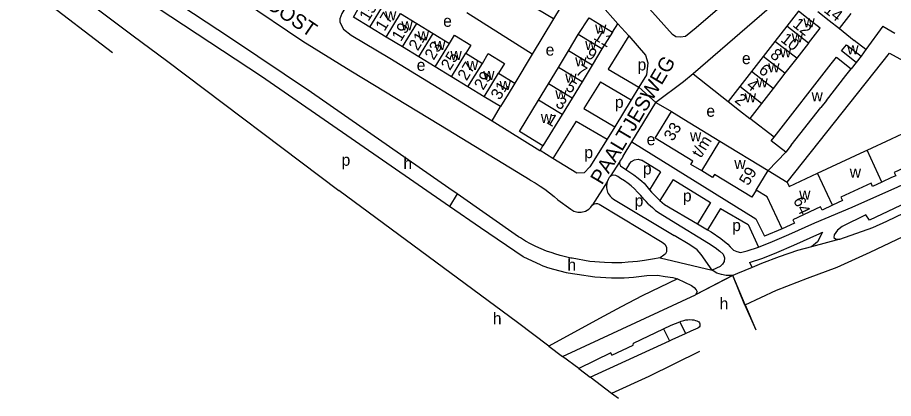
# Model space of a CAD drawing. Extents: x 158356 to 159894, y 383831 to 385260.
# Drawn here: x 158701.2 to 159000.7, y 383830.9 to 383961.2 of the extents above; entities that cross this region are included whole.
import ezdxf

# ---------------------------------------------------------------- set-up
doc = ezdxf.new("R2010")
doc.units = 0
for name, color, linetype in [('BLT_Basislijn', 7, 'Continuous'), ('BLT_Bebouwing', 7, 'Continuous'), ('BLT_Centroide', 7, 'Continuous'), ('BLT_Huisnummer', 7, 'Continuous'), ('BLT_Huisnummer_ tussenligend', 7, 'Continuous'), ('BLT_Huisnummer_reeks', 7, 'Continuous'), ('BLT_Onderverdeling_panden', 7, 'Continuous'), ('BLT_Straatnaam', 7, 'Continuous'), ('BLT_Vlakafsluiter', 7, 'Continuous')]:
    doc.layers.add(name, color=color, linetype=linetype)

msp = doc.modelspace()

# ---------------------------------------------------------------- linework, layer by layer
at = {"layer": 'BLT_Basislijn'}
for p, q in [((158733.69, 383949.17), (158656.47, 384008.34)), ((158964.85, 383970.22), (158932.17, 383941.98)), ((158900.43, 383965.89), (158906.43, 383959.08)), ((158877.21, 383948.71), (158854.87, 383962.79)), ((158884.43, 383960.73), (158877.21, 383948.71)), ((158904.67, 383956.2), (158906.43, 383959.08)), ((158982.23, 383957.43), (158987.21, 383953.4)), ((158997.04, 383958.25), (159001.16, 383955.84)), ((158910.26, 383954.96), (158903.18, 383943.54)), ((158991.28, 383950.26), (158987.21, 383953.4)), ((158877.21, 383948.71), (158871.25, 383938.8)), ((158964.3, 383904.94), (158999.29, 383949)), ((158991.28, 383950.26), (158989.64, 383947.99)), ((158999.29, 383949), (159026.07, 383934.41)), ((158987.98, 383945.88), (158986.26, 383943.69)), ((158903.18, 383943.54), (158913.66, 383937.37)), ((158900.54, 383939.29), (158894.84, 383930.09)), ((158900.54, 383939.29), (158911.04, 383933.11)), ((158932.17, 383941.98), (158944.12, 383932.51)), ((158913.66, 383937.37), (158911.04, 383933.11)), ((158863.52, 383925.87), (158866.36, 383930.76)), ((158911.04, 383933.11), (158905.38, 383923.88)), ((158911.26, 383918.68), (158919.49, 383932.21)), ((158919.49, 383932.21), (158924.77, 383929.08)), ((158894.84, 383930.09), (158905.38, 383923.88)), ((158892.2, 383925.84), (158884.28, 383913.06)), ((158892.2, 383925.84), (158902.76, 383919.62)), ((158959.92, 383920.35), (158951.54, 383926.73)), ((158876.46, 383905.62), (158845.77, 383924.27)), ((158905.38, 383923.88), (158902.76, 383919.62)), ((158908.28, 383913.84), (158911.26, 383918.68)), ((158879.88, 383915.72), (158880.83, 383917.4)), ((158884.28, 383913.06), (158879.88, 383915.72)), ((158921.07, 383908.42), (158914.49, 383912.44)), ((158910.33, 383911.08), (158909.21, 383909.23)), ((158921.07, 383908.42), (158917.27, 383902.35)), ((158925.34, 383905.81), (158920.82, 383898.6)), ((158925.34, 383905.81), (158938.13, 383897.97)), ((158872.16, 383856.91), (158811.09, 383902.1)), ((158851.48, 383900.89), (158848.65, 383902.86)), ((158872.54, 383886.2), (158851.48, 383900.89)), ((158885.96, 383898.88), (158890.33, 383895.73)), ((158905.02, 383899.09), (158925.71, 383886.66)), ((158938.13, 383897.97), (158933.64, 383890.68)), ((158941.59, 383895.96), (158937.09, 383888.66)), ((158941.59, 383895.96), (158951.06, 383890.42)), ((158951.06, 383890.42), (158954.57, 383882.71)), ((158962.68, 383888.99), (158956.54, 383886.44)), ((158951.51, 383877.47), (158952.37, 383875.72)), ((158887.51, 383845.34), (158932.98, 383866.36)), ((158882.83, 383848.86), (158872.16, 383856.91)), ((158927.61, 383857.11), (158929.6, 383853.17)), ((158922.02, 383854.74), (158924.07, 383850.6)), ((158882.83, 383848.86), (158887.51, 383845.34)), ((158893.06, 383841.15), (158887.51, 383845.34)), ((158893.06, 383841.15), (158897.01, 383838.18)), ((158904.33, 383832.66), (158897.01, 383838.18)), ((158906.63, 383830.93), (158904.33, 383832.66))]:
    msp.add_line(p, q, dxfattribs=at)
for points in [[(158658.2, 384017.9), (158708.3, 383979.52), (158740.71, 383955.02), (158752.16, 383946.49), (158811.09, 383902.1)], [(158845.77, 383924.27), (158815.12, 383942.93), (158798.74, 383953.03), (158757.49, 383980.97), (158706.27, 384015.3)], [(158957.8, 384013.41), (158976.75, 384003.11), (158977.59, 384001.79), (158978.2, 383998.68), (158977.76, 383997.43), (158976.65, 383995.8), (158964.84, 383984.91), (158933.18, 383957.74), (158929.53, 383954.78), (158927.87, 383954.47), (158926.29, 383954.61), (158925.11, 383955.45), (158909.46, 383973.08)], [(158848.65, 383902.86), (158801.74, 383935.63), (158773.98, 383954.21), (158744.72, 383973.5), (158719.42, 383989.69)], [(158848.91, 383896.59), (158784.62, 383941.05), (158735.9, 383973.27)], [(158814.16, 383966.01), (158812.13, 383962.64), (158811.34, 383960.74), (158811.34, 383959.69), (158812.63, 383957.28), (158815.24, 383955.2), (158828.49, 383947.37), (158863.52, 383925.87)], [(158906.43, 383959.08), (158910.26, 383954.96)], [(158997.04, 383958.25), (158991.28, 383950.26)], [(158910.26, 383954.96), (158915.92, 383948.41), (158916.7, 383945.79), (158916.27, 383941.62), (158913.66, 383937.37)], [(158932.17, 383941.98), (158928.94, 383939.19), (158919.49, 383932.21)], [(158863.52, 383925.87), (158879.74, 383915.8), (158879.88, 383915.72)], [(158949.95, 383862.91), (158960.72, 383867.95), (158971.31, 383872.04), (158981.41, 383875.89), (158992.71, 383880.94), (159088.93, 383926.66)], [(158973.85, 383891.02), (158986.52, 383896.41), (159002.13, 383903.34), (159020.44, 383911.89), (159042.83, 383922.34), (159045.95, 383923.82)], [(158902.76, 383919.62), (158896.92, 383910.11), (158894.94, 383908.15), (158892.48, 383908.05), (158884.28, 383913.06)], [(158911.26, 383918.68), (158953.65, 383892.43), (158956.54, 383886.44)], [(159053.28, 383920.71), (158992.49, 383891.93), (158991.27, 383893.7), (158983.13, 383889.76), (158981.5, 383888.54), (158980.42, 383886.91), (158980.28, 383885.96), (158980.96, 383885.42), (158982.35, 383885.39)], [(158982.35, 383885.39), (158993.58, 383889.36), (158998.46, 383891.53), (159004.3, 383894.38), (159021.53, 383902.66), (159051.79, 383917.05)], [(158908.28, 383913.84), (158907.77, 383913.05), (158907.29, 383912.31), (158907.1, 383911.94)], [(158910.33, 383911.08), (158911.07, 383911.99), (158912.15, 383912.6), (158913.38, 383912.74), (158914.49, 383912.44)], [(158957.8, 383908.91), (158963.84, 383915.17)], [(158907.1, 383911.94), (158907.02, 383911.45), (158907.1, 383910.97), (158907.4, 383910.45), (158909.21, 383909.23)], [(158903.83, 383906.89), (158903.5, 383906.48), (158903.13, 383905.85), (158902.83, 383905.07)], [(158916.99, 383897.41), (158916.12, 383898.28), (158915.34, 383899.09), (158914.3, 383900.32), (158913.22, 383901.54), (158912.18, 383902.66), (158911.03, 383903.66), (158909.96, 383904.51), (158908.73, 383905.36), (158907.36, 383906.18), (158906.43, 383906.85), (158905.73, 383907.22), (158905.06, 383907.33), (158904.35, 383907.18), (158903.83, 383906.89)], [(158909.21, 383909.23), (158911.92, 383907.48), (158913.41, 383906.33), (158914.6, 383905.29), (158915.41, 383904.55), (158917.27, 383902.35)], [(158876.46, 383905.62), (158878.18, 383904.64), (158879.87, 383903.59), (158881.51, 383902.47), (158883.1, 383901.28), (158884.64, 383900.03), (158885.96, 383898.88)], [(158902.83, 383905.07), (158902.68, 383904.48), (158902.57, 383903.7), (158902.57, 383903.06), (158902.72, 383902.4), (158902.94, 383901.54), (158903.2, 383900.99), (158903.8, 383900.09), (158904.39, 383899.58), (158905.02, 383899.09)], [(158917.27, 383902.35), (158917.94, 383901.54)], [(158917.94, 383901.54), (158920.82, 383898.6)], [(158897.82, 383897.14), (158898.33, 383897.49), (158898.93, 383897.64), (158899.54, 383897.64), (158900.04, 383897.39), (158921.63, 383884.44), (158922.48, 383883.69), (158923.04, 383882.74), (158923.14, 383881.88), (158923.09, 383881.08), (158922.79, 383880.37), (158922.22, 383879.93), (158920.92, 383879.06)], [(158916.99, 383897.41), (158918.29, 383896.2), (158919.37, 383895.27), (158920.89, 383894.23), (158924.82, 383891.85)], [(158920.82, 383898.6), (158922.44, 383897.33), (158933.64, 383890.68)], [(158880.24, 383876.48), (158874.09, 383879.35), (158859.5, 383889.27), (158848.91, 383896.59)], [(158890.33, 383895.73), (158891.43, 383895.02), (158892.74, 383894.62), (158893.95, 383894.62), (158895.41, 383894.97), (158896.52, 383895.63), (158897.22, 383896.33), (158897.82, 383897.14)], [(158924.82, 383891.85), (158937.43, 383884.08), (158939.77, 383882.63), (158941.33, 383881.29), (158942.44, 383880.29), (158942.89, 383879.06), (158942.78, 383877.73), (158942.22, 383876.84), (158941.44, 383876.06), (158938.68, 383874.81)], [(158933.64, 383890.68), (158937.09, 383888.66)], [(158937.09, 383888.66), (158938.34, 383887.93), (158941.68, 383885.7), (158944.02, 383883.7), (158944.91, 383882.8), (158946.02, 383881.69), (158947.14, 383881.25), (158948.36, 383880.91), (158950.62, 383881.4)], [(158954.57, 383882.71), (158959.32, 383884.59), (158964.95, 383887.02), (158973.85, 383891.02)], [(158883.96, 383880.7), (158882.08, 383881.37), (158880.22, 383882.11), (158878.39, 383882.94), (158876.6, 383883.83), (158874.84, 383884.79), (158873.13, 383885.83), (158872.54, 383886.2)], [(158938.68, 383874.81), (158934.94, 383880.2), (158933.6, 383881.76), (158931.04, 383883.43), (158925.71, 383886.66)], [(158951.51, 383877.47), (158955.98, 383878.97), (158960.85, 383880.89), (158966.57, 383883.36), (158975.49, 383887.37)], [(158975.49, 383887.37), (158976.48, 383887.86), (158974.72, 383884.47), (158972.64, 383882.77)], [(158950.62, 383881.4), (158954.57, 383882.71)], [(158972.64, 383882.77), (158967.89, 383881.54), (158961.65, 383879.42), (158955.53, 383877.08), (158952.37, 383875.72)], [(158890.81, 383878.9), (158890.4, 383878.97), (158888.53, 383879.36), (158886.69, 383879.84), (158884.86, 383880.39), (158883.96, 383880.7)], [(158880.24, 383876.48), (158882.35, 383875.76), (158884.48, 383875.12), (158886.64, 383874.55), (158888.81, 383874.07), (158891, 383873.66), (158892.57, 383873.43)], [(158920.92, 383879.06), (158918.26, 383878.56), (158915.54, 383878.11), (158913.17, 383877.75), (158910, 383877.5), (158907.79, 383877.35), (158904.37, 383877.3), (158901.85, 383877.4), (158896.82, 383877.75), (158890.81, 383878.9)], [(158892.57, 383873.43), (158898.58, 383872.58), (158904.27, 383872.23), (158908.64, 383872.18), (158911.76, 383872.38), (158914.58, 383872.73), (158916.39, 383873.03)], [(158945.63, 383872.96), (158943.51, 383872.96), (158941.84, 383873.29), (158940.28, 383873.74), (158938.68, 383874.81)], [(158952.37, 383875.72), (158947.36, 383873.65), (158945.78, 383872.98)], [(158926.81, 383871.89), (158914.79, 383866.01), (158907.55, 383862.24), (158900.15, 383858.31), (158882.83, 383848.86)], [(158916.39, 383873.03), (158920.04, 383873.11)], [(158920.04, 383873.11), (158922.64, 383872.66), (158925.21, 383872.36), (158926.81, 383871.89)], [(158926.81, 383871.89), (158929.26, 383870.73), (158931.6, 383869.62), (158932.6, 383868.84), (158933.27, 383868.06), (158933.6, 383867.39), (158933.03, 383866.44)], [(158945.74, 383872.96), (158945.63, 383872.96)], [(158945.78, 383872.98), (158945.74, 383872.96)], [(158933.03, 383866.44), (158932.98, 383866.36)], [(158949.9, 383862.89), (158949.95, 383862.91)], [(158922.02, 383854.74), (158924.65, 383855.96), (158927.61, 383857.11)], [(158927.61, 383857.11), (158928.16, 383857.32), (158929.06, 383857.65), (158929.68, 383857.79), (158930.35, 383857.88), (158931.01, 383857.92), (158931.81, 383857.88), (158932.38, 383857.79), (158932.97, 383857.66), (158933.49, 383857.51), (158933.92, 383857.31), (158934.18, 383857.17), (158934.41, 383856.85), (158934.52, 383856.42), (158934.54, 383855.93), (158934.44, 383855.63), (158934.29, 383855.36), (158933.96, 383855.14)], [(158911.68, 383849.18), (158911.77, 383849.85), (158922.02, 383854.74)], [(158924.07, 383850.6), (158925.06, 383851.06), (158929.6, 383853.17)], [(158929.6, 383853.17), (158931.55, 383854.08), (158933.96, 383855.14)], [(158897.01, 383838.18), (158924.07, 383850.6)], [(158904.45, 383845.74), (158904.07, 383846.53), (158893.06, 383841.15)], [(158934.4, 383846.95), (158917.1, 383838.48), (158904.33, 383832.66)], [(158904.45, 383845.74), (158911.68, 383849.18)]]:
    msp.add_lwpolyline(points, dxfattribs=at)
at = {"layer": 'BLT_Bebouwing'}
for p, q in [((158884.43, 383960.73), (158878.84, 383964.13)), ((158832.09, 383962.61), (158837.69, 383959.2)), ((158982.23, 383957.43), (158986.27, 383962.6)), ((158827.21, 383954.57), (158821.7, 383957.91)), ((158837.69, 383959.2), (158843.28, 383955.8)), ((158964.2, 383958.23), (158960.18, 383953.09)), ((158832.8, 383951.17), (158827.21, 383954.57)), ((158843.28, 383955.8), (158848.87, 383952.4)), ((158889.53, 383949.8), (158892.93, 383955.41)), ((158904.67, 383956.2), (158901.03, 383950.49)), ((158960.18, 383953.09), (158956.17, 383947.94)), ((158971.61, 383952.44), (158967.6, 383947.3)), ((158838.39, 383947.77), (158832.8, 383951.17)), ((158854.47, 383949), (158860.15, 383945.55)), ((158886.13, 383944.19), (158889.53, 383949.8)), ((158901.03, 383950.49), (158897.62, 383944.89)), ((158843.99, 383944.36), (158838.39, 383947.77)), ((158956.17, 383947.94), (158952.15, 383942.8)), ((158967.6, 383947.3), (158963.58, 383942.16)), ((158989.64, 383947.99), (158987.98, 383945.88)), ((158849.58, 383940.97), (158843.99, 383944.36)), ((158882.72, 383938.59), (158886.13, 383944.19)), ((158897.62, 383944.89), (158894.22, 383939.28)), ((158952.15, 383942.8), (158948.14, 383937.66)), ((158984.46, 383941.4), (158986.26, 383943.69)), ((158855.18, 383937.57), (158849.58, 383940.97)), ((158865.65, 383942.2), (158871.25, 383938.8)), ((158894.22, 383939.28), (158890.82, 383933.67)), ((158963.58, 383942.16), (158959.57, 383937.01)), ((158977.74, 383932.85), (158984.46, 383941.4)), ((158860.77, 383934.16), (158855.18, 383937.57)), ((158879.32, 383932.98), (158882.72, 383938.59)), ((158948.14, 383937.66), (158944.12, 383932.51)), ((158959.57, 383937.01), (158955.55, 383931.87)), ((158866.36, 383930.76), (158860.77, 383934.16)), ((158890.82, 383933.67), (158887.41, 383928.07)), ((158955.55, 383931.87), (158951.54, 383926.73)), ((158965.7, 383917.54), (158975.88, 383930.49)), ((158977.74, 383932.85), (158975.88, 383930.49)), ((158887.41, 383928.07), (158880.83, 383917.4)), ((158941.36, 383918.95), (158957.8, 383908.91)), ((158965.7, 383917.54), (158963.84, 383915.17)), ((158974.7, 383907.99), (158990.88, 383915.51)), ((158990.88, 383915.51), (158991.69, 383915.89)), ((158979.8, 383897), (158976.32, 383895.39))]:
    msp.add_line(p, q, dxfattribs=at)
for points in [[(158889.32, 383968.77), (158886.73, 383964.5), (158884.43, 383960.73)], [(158821.7, 383957.91), (158816.02, 383961.37), (158817.58, 383963.93)], [(158971.61, 383952.44), (158975.62, 383957.58), (158972.15, 383960.29), (158968.21, 383963.37), (158964.2, 383958.23)], [(158974.79, 383963.24), (158978.73, 383960.16), (158982.23, 383957.43)], [(158892.93, 383955.41), (158896.62, 383961.1), (158897.23, 383960.73), (158904.67, 383956.2)], [(158848.87, 383952.4), (158850.57, 383955.18), (158856.16, 383951.78), (158854.47, 383949)], [(158987.98, 383945.88), (158982.97, 383949.81), (158984.63, 383951.93), (158989.64, 383947.99)], [(158860.15, 383945.55), (158862.17, 383948.88), (158867.74, 383945.5), (158865.65, 383942.2)], [(158959.92, 383920.35), (158979.4, 383945.38), (158981.2, 383947.67), (158986.26, 383943.69)], [(158871.25, 383938.8), (158868.96, 383935.04), (158866.36, 383930.76)], [(158880.83, 383917.4), (158872.81, 383922.3), (158879.32, 383932.98)], [(158944.12, 383932.51), (158948.06, 383929.44), (158951.54, 383926.73)], [(158935.13, 383908.74), (158931.41, 383911.01), (158932.07, 383912.1), (158919.2, 383919.95), (158924.77, 383929.08)], [(158924.77, 383929.08), (158929.04, 383926.48), (158941.36, 383918.95)], [(158991.69, 383915.89), (159000, 383919.75), (159009.73, 383924.32)], [(158963.84, 383915.17), (158958.9, 383919.05), (158959.92, 383920.35)], [(159014.85, 383913.41), (159010.96, 383911.58), (159010.43, 383912.72), (159000.92, 383908.26), (159001.45, 383907.13), (159000, 383906.46), (158996.77, 383904.96)], [(158953.73, 383902.24), (158952.24, 383899.79), (158939.51, 383907.55), (158938.85, 383906.47), (158935.13, 383908.74)], [(158957.8, 383908.91), (158964.3, 383904.94)], [(158964.3, 383904.94), (158964.98, 383903.47), (158974.7, 383907.99)], [(158996.77, 383904.96), (158993.54, 383903.46), (158993.03, 383904.56), (158982.75, 383899.78), (158983.28, 383898.62), (158979.8, 383897)], [(158962.68, 383888.99), (158957.55, 383899.91), (158953.73, 383902.24)], [(158976.32, 383895.39), (158975.8, 383896.52), (158966.25, 383892.08), (158966.8, 383890.9), (158962.68, 383888.99)]]:
    msp.add_lwpolyline(points, dxfattribs=at)
at = {"layer": 'BLT_Onderverdeling_panden'}
for p, q in [((158821.7, 383957.91), (158826.59, 383965.95)), ((158827.21, 383954.57), (158832.09, 383962.61)), ((158832.8, 383951.17), (158837.69, 383959.2)), ((158971.61, 383952.44), (158964.2, 383958.23)), ((158838.39, 383947.77), (158843.28, 383955.8)), ((158901.03, 383950.49), (158892.93, 383955.41)), ((158843.99, 383944.36), (158848.87, 383952.4)), ((158967.6, 383947.3), (158960.18, 383953.09)), ((158849.58, 383940.97), (158854.47, 383949)), ((158897.62, 383944.89), (158889.53, 383949.8)), ((158855.18, 383937.57), (158860.15, 383945.55)), ((158963.58, 383942.16), (158956.17, 383947.94)), ((158894.22, 383939.28), (158886.13, 383944.19)), ((158959.57, 383937.01), (158952.15, 383942.8)), ((158860.77, 383934.16), (158865.65, 383942.2)), ((158890.82, 383933.67), (158882.72, 383938.59)), ((158955.55, 383931.87), (158948.14, 383937.66)), ((158887.41, 383928.07), (158879.32, 383932.98)), ((158935.13, 383908.74), (158941.36, 383918.95)), ((158996.77, 383904.96), (158991.69, 383915.89)), ((158953.73, 383902.24), (158957.8, 383908.91)), ((158979.8, 383897), (158974.7, 383907.99))]:
    msp.add_line(p, q, dxfattribs=at)
at = {"layer": 'BLT_Vlakafsluiter'}
for p, q in [((158913.66, 383937.37), (158919.49, 383932.21)), ((158907.1, 383911.94), (158903.83, 383906.89)), ((158902.83, 383905.07), (158897.82, 383897.14)), ((158851.48, 383900.89), (158848.91, 383896.59)), ((158982.35, 383885.39), (158972.64, 383882.77)), ((158920.92, 383879.06), (158938.68, 383874.81)), ((158945.74, 383872.96), (158932.98, 383866.36)), ((158945.63, 383872.96), (158933.03, 383866.44)), ((158949.9, 383862.89), (158945.74, 383872.96)), ((158949.95, 383862.91), (158945.78, 383872.98)), ((158949.9, 383862.89), (158953.58, 383854.42)), ((158949.95, 383862.91), (158953.63, 383854.44))]:
    msp.add_line(p, q, dxfattribs=at)

# ---------------------------------------------------------------- texts
at = {"layer": 'BLT_Centroide'}
for s, p in [('w', (158826.86, 383960.28)), ('e', (158846.73, 383958.06)), ('w', (158969.91, 383957.91)), ('w', (158832.45, 383956.88)), ('w', (158898.68, 383955.75)), ('w', (158838.03, 383953.48)), ('w', (158965.9, 383952.75)), ('w', (158843.64, 383950.09)), ('e', (158881.77, 383948.21)), ('w', (158895.27, 383950.16)), ('w', (158984.88, 383948.63)), ('w', (158849.23, 383946.69)), ('e', (158948.88, 383945.29)), ('w', (158961.88, 383947.62)), ('e', (158837.68, 383942.99)), ('w', (158854.83, 383943.28)), ('w', (158891.88, 383944.53)), ('p', (158913.2, 383943.15)), ('w', (158957.87, 383942.47)), ('w', (158860.42, 383939.88)), ('w', (158866.02, 383936.48)), ('w', (158888.48, 383938.94)), ('w', (158953.85, 383937.34)), ('w', (158885.07, 383933.31)), ('p', (158905.45, 383930.34)), ('w', (158949.84, 383932.19)), ('w', (158972.68, 383932.62)), ('e', (158936.72, 383927.29)), ('w', (158880.11, 383925.17)), ('w', (158931.11, 383918.91)), ('e', (158916.3, 383917.56)), ('p', (158895, 383913.14)), ('p', (158812, 383910.53)), ('h', (158833.13, 383909.38)), ('w', (158946.28, 383909.38)), ('p', (158915.02, 383907.57)), ('w', (158985.74, 383906.44)), ('p', (158928.7, 383898.31)), ('w', (158968.45, 383898.94)), ('p', (158912.19, 383896.62)), ('p', (158945.55, 383888.19)), ('h', (158889.2, 383874.64)), ('h', (158941.25, 383861.38)), ('h', (158863.71, 383856.33))]:
    msp.add_text(s, height=4, dxfattribs=at).set_placement(p)
at = {"layer": 'BLT_Huisnummer'}
for s, rotation, p in [('15', 58.7061, (158821.18, 383959.74)), ('14', 322.0185, (158976.63, 383963.29)), ('12', 322.0185, (158965.96, 383958.37)), ('19', 58.7061, (158832.28, 383952.8)), ('11', 328.7425, (158897.88, 383953.96)), ('23', 58.7061, (158843.5, 383946.42)), ('27', 58.7061, (158854.74, 383939.37)), ('6', 322.0185, (158954.31, 383942.63)), ('5', 328.7425, (158888.28, 383936.65)), ('31', 58.7061, (158866.1, 383932.78)), ('2', 322.0185, (158946.14, 383932.55)), ('1', 328.7425, (158881.74, 383925.28))]:
    msp.add_text(s, height=4, rotation=rotation, dxfattribs=at).set_placement(p)
at = {"layer": 'BLT_Huisnummer_ tussenligend'}
for s, rotation, p in [('17', 58.7061, (158826.68, 383956.33)), ('21', 58.7061, (158838.04, 383949.61)), ('10', 322.0185, (158961.85, 383953.23)), ('25', 58.7061, (158849.06, 383942.91)), ('9', 328.7425, (158895.18, 383947.83)), ('8', 322.0185, (158958.24, 383947.9)), ('7', 328.7425, (158891.78, 383942.04)), ('29', 58.7061, (158860.42, 383936.16)), ('4', 322.0185, (158950.11, 383937.54)), ('3', 328.7425, (158884.86, 383931.01))]:
    msp.add_text(s, height=4, rotation=rotation, dxfattribs=at).set_placement(p)
at = {"layer": 'BLT_Huisnummer_reeks'}
for s, rotation, p in [('33', 58.6181, (158925.28, 383918.69)), ('t/m', 58.6181, (158934.85, 383912.93)), ('59', 58.616, (158951.04, 383903.45)), ('64', 294.9377, (158966.34, 383898.77))]:
    msp.add_text(s, height=4, rotation=rotation, dxfattribs=at).set_placement(p)
at = {"layer": 'BLT_Straatnaam'}
for s, height, rotation, p in [('TILBURGSEWEG-OOST', 4.9999, 325.862, (158739.25, 383996.39)), ('PAALTJESWEG', 5, 59.1825, (158901.02, 383903.72))]:
    msp.add_text(s, height=height, rotation=rotation, dxfattribs=at).set_placement(p)

doc.saveas('drawing.dxf')
